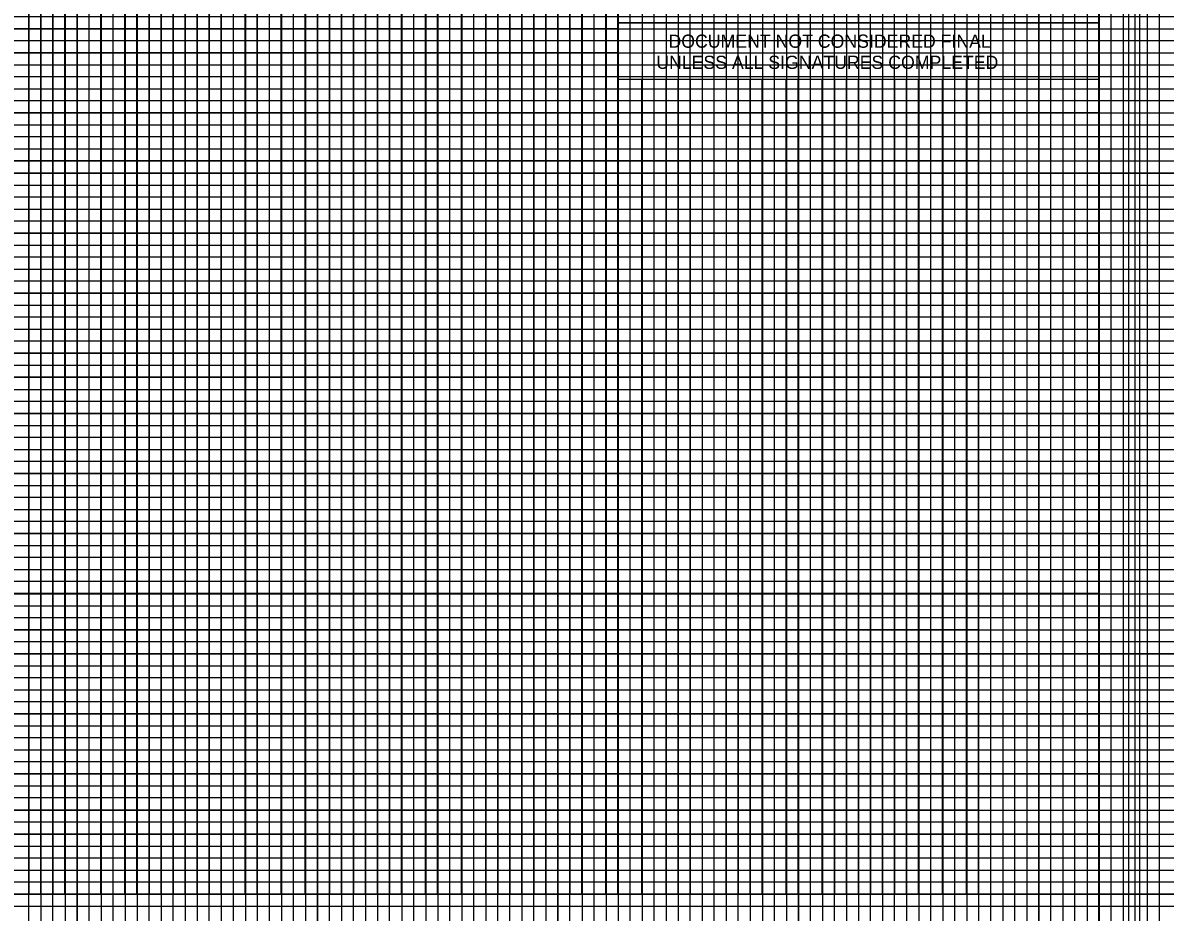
# Model space of a CAD drawing. Extents: x 553912 to 567693, y 512355 to 537539.
# Drawn here: x 566753.9 to 567228.9, y 513957.2 to 514327.2 of the extents above; entities that cross this region are included whole.
import ezdxf

# ---------------------------------------------------------------- set-up
doc = ezdxf.new("R2010")
doc.units = 0
for name, color, linetype in [('Old_Level_42', 7, 'Continuous'), ('Old_Level_54', 7, 'Continuous'), ('Prop ROW Permanent Easement CELL', 7, 'Continuous'), ('Sheet DOT Grid CELL', 7, 'Continuous'), ('Sheet Layout Profile Border Port 1', 7, 'Continuous'), ('Sheet Plot Border Inside CELL', 7, 'Continuous'), ('Sheet Plot Border Outside CELL', 7, 'Continuous'), ('Sheet Profile CELL', 7, 'Continuous'), ('Sheet Profile Grid Major CELL', 7, 'Continuous'), ('Sheet Profile Grid Middle CELL', 7, 'Continuous'), ('Sheet Profile Grid Minor CELL', 7, 'Continuous'), ('Sheet Sticker Exception Certification CELL', 7, 'Continuous'), ('Sheet Summary Guardrail CELL', 7, 'Continuous')]:
    doc.layers.add(name, color=color, linetype=linetype)

msp = doc.modelspace()

# ---------------------------------------------------------------- linework, layer by layer
at = {"layer": 'Old_Level_42'}
for p, q in [((566776.42, 514839.71), (566776.42, 513814.71)), ((566826.42, 514839.71), (566826.42, 513814.71)), ((566876.42, 514839.71), (566876.42, 513814.71)), ((566926.42, 514839.71), (566926.42, 513814.71)), ((566976.42, 514839.71), (566976.42, 513814.71)), ((567026.42, 514839.71), (567026.42, 513814.71)), ((567076.42, 514839.71), (567076.42, 513814.71)), ((567126.42, 514839.71), (567126.42, 513814.71)), ((567176.42, 514839.71), (567176.42, 513814.71)), ((567226.42, 514839.71), (567226.42, 513814.71)), ((566176.42, 514314.71), (567676.42, 514314.71)), ((566176.42, 514264.71), (567676.42, 514264.71)), ((566176.42, 514214.71), (567676.42, 514214.71)), ((566176.42, 514164.71), (567676.42, 514164.71)), ((566176.42, 514114.71), (567676.42, 514114.71)), ((566176.42, 514064.71), (567676.42, 514064.71)), ((566176.42, 514014.71), (567676.42, 514014.71)), ((566176.42, 513964.71), (567676.42, 513964.71))]:
    msp.add_line(p, q, dxfattribs=at)
at = {"layer": 'Old_Level_54'}
for points in [[(566776.42, 513814.71), (566776.42, 514839.71), (566826.42, 514839.71), (566826.42, 513814.71)], [(566876.42, 513814.71), (566876.42, 514839.71), (566926.42, 514839.71), (566926.42, 513814.71)], [(566976.42, 513814.71), (566976.42, 514839.71), (567026.42, 514839.71), (567026.42, 513814.71)], [(567076.42, 513814.71), (567076.42, 514839.71), (567126.42, 514839.71), (567126.42, 513814.71)], [(567176.42, 513814.71), (567176.42, 514839.71), (567226.42, 514839.71), (567226.42, 513814.71)], [(567676.42, 514264.71), (566176.42, 514264.71), (566176.42, 514314.71), (567676.42, 514314.71)], [(567676.42, 514164.71), (566176.42, 514164.71), (566176.42, 514214.71), (567676.42, 514214.71)], [(567676.42, 514064.71), (566176.42, 514064.71), (566176.42, 514114.71), (567676.42, 514114.71)], [(567676.42, 513964.71), (566176.42, 513964.71), (566176.42, 514014.71), (567676.42, 514014.71)]]:
    msp.add_lwpolyline(points, dxfattribs=at)
at = {"layer": 'Prop ROW Permanent Easement CELL'}
for points in [[(566751.42, 514839.71), (566801.42, 514839.71), (566801.42, 513814.71)], [(566851.42, 513814.71), (566851.42, 514839.71), (566901.42, 514839.71), (566901.42, 513814.71)], [(566951.42, 513814.71), (566951.42, 514839.71), (567001.42, 514839.71), (567001.42, 513814.71)], [(567051.42, 513814.71), (567051.42, 514839.71), (567101.42, 514839.71), (567101.42, 513814.71)], [(567151.42, 513814.71), (567151.42, 514839.71), (567201.42, 514839.71), (567201.42, 513814.71)], [(567676.42, 514339.71), (566176.42, 514339.71), (566176.42, 514289.71), (567676.42, 514289.71)], [(567676.42, 514239.71), (566176.42, 514239.71), (566176.42, 514189.71), (567676.42, 514189.71)], [(567676.42, 514139.71), (566176.42, 514139.71), (566176.42, 514089.71), (567676.42, 514089.71)], [(567676.42, 514039.71), (566176.42, 514039.71), (566176.42, 513989.71), (567676.42, 513989.71)]]:
    msp.add_lwpolyline(points, dxfattribs=at)
at = {"layer": 'Sheet DOT Grid CELL'}
for p, q in [((566801.35, 513964.72), (566801.35, 514464.72)), ((566851.35, 513964.72), (566851.35, 514464.72)), ((566901.35, 513964.72), (566901.35, 514464.72)), ((566951.35, 513964.72), (566951.35, 514464.72)), ((567001.35, 513964.72), (567001.35, 514327.17)), ((567001.35, 514314.72), (565701.35, 514314.72)), ((567051.35, 513964.72), (567051.35, 514303.67)), ((567101.35, 513964.72), (567101.35, 514303.67)), ((567151.35, 513964.72), (567151.35, 514303.67)), ((567201.35, 514264.72), (565701.35, 514264.72)), ((567201.35, 514214.72), (565701.35, 514214.72)), ((567201.35, 514164.72), (565701.35, 514164.72)), ((567201.35, 514114.72), (565701.35, 514114.72)), ((567201.35, 514064.72), (565701.35, 514064.72)), ((567201.35, 514014.72), (565701.35, 514014.72))]:
    msp.add_line(p, q, dxfattribs=at)
at = {"layer": 'Sheet Layout Profile Border Port 1'}
msp.add_lwpolyline([(565751.35, 514303.67), (565751.35, 513964.72), (567151.35, 513964.72), (567151.35, 514303.67)], dxfattribs=at)
at = {"layer": 'Sheet Plot Border Inside CELL'}
msp.add_lwpolyline([(565547.35, 513412.17), (567213.85, 513412.17), (567213.85, 514467.27), (565547.35, 514467.27)], close=True, dxfattribs=at)
at = {"layer": 'Sheet Plot Border Outside CELL'}
msp.add_lwpolyline([(565534.35, 513389.72), (567218.35, 513389.72), (567218.35, 514489.72), (565534.35, 514489.72)], close=True, dxfattribs=at)
at = {"layer": 'Sheet Profile CELL'}
msp.add_line((565701.35, 513964.72), (567201.35, 513964.72), dxfattribs=at)
for points in [[(567201.35, 514464.72), (565701.35, 514464.72), (565701.35, 513414.72), (567201.35, 513414.72)], [(567001.3, 514439.67), (567101.35, 514439.67), (567101.35, 514327.17), (567001.3, 514327.17)], [(567101.35, 514439.67), (567201.35, 514439.67), (567201.35, 514327.17), (567101.35, 514327.17)]]:
    msp.add_lwpolyline(points, close=True, dxfattribs=at)
at = {"layer": 'Sheet Profile Grid Major CELL'}
for points in [[(566751.35, 513964.72), (566801.35, 513964.72), (566801.35, 514464.72), (566851.35, 514464.72), (566851.35, 513964.72), (566901.35, 513964.72), (566901.35, 514464.72), (566951.35, 514464.72), (566951.35, 513964.72), (567001.35, 513964.72), (567001.35, 514464.72), (567027.65, 514464.72)], [(567001.35, 514364.72), (565701.35, 514364.72), (565701.35, 514314.72), (567001.35, 514314.72)], [(567151.35, 514303.67), (567151.35, 513964.72), (567201.35, 513964.72), (567201.35, 514314.72)], [(567051.35, 514303.67), (567051.35, 513964.72), (567101.35, 513964.72), (567101.35, 513964.72), (567101.35, 514303.67)], [(567201.35, 514264.72), (565701.35, 514264.72), (565701.35, 514214.72), (567201.35, 514214.72)], [(567201.35, 514164.72), (565701.35, 514164.72), (565701.35, 514114.72), (567201.35, 514114.72)], [(567201.35, 514064.72), (565701.35, 514064.72), (565701.35, 514064.72), (565701.35, 514014.72), (567201.35, 514014.72)]]:
    msp.add_lwpolyline(points, dxfattribs=at)
at = {"layer": 'Sheet Profile Grid Middle CELL'}
for points in [[(566726.35, 514464.72), (566776.35, 514464.72), (566776.35, 513964.72), (566826.35, 513964.72), (566826.35, 514464.72), (566876.35, 514464.72), (566876.35, 513964.72), (566926.35, 513964.72), (566926.35, 514464.72), (566976.35, 514464.72), (566976.35, 513964.72), (567026.35, 513964.72), (567026.35, 514303.67)], [(567026.35, 514227.52), (567026.35, 513964.72), (567076.35, 513964.72), (567076.35, 514303.67)], [(567076.35, 514227.52), (567076.35, 513964.72), (567126.35, 513964.72), (567126.35, 514303.67)], [(567201.35, 514289.72), (565701.35, 514289.72), (565701.35, 514239.72), (567026.35, 514239.72)], [(567026.35, 514239.72), (567201.35, 514239.72)], [(567201.35, 514189.72), (565701.35, 514189.72), (565701.35, 514139.72), (567201.35, 514139.72)], [(567201.35, 514089.72), (565701.35, 514089.72), (565701.35, 514039.72), (567201.35, 514039.72)], [(567201.35, 513989.72), (565701.35, 513989.72)]]:
    msp.add_lwpolyline(points, dxfattribs=at)
at = {"layer": 'Sheet Profile Grid Minor CELL'}
for p, q in [((567001.35, 514324.72), (565751.35, 514324.72)), ((567001.35, 514319.72), (565751.35, 514319.72)), ((565751.35, 514309.72), (567001.35, 514309.72)), ((567001.35, 514304.72), (565751.35, 514304.72)), ((565751.35, 514299.72), (567151.35, 514299.72)), ((567151.35, 514279.72), (565751.35, 514279.72)), ((565751.35, 514274.72), (567151.35, 514274.72)), ((567151.35, 514254.72), (565751.35, 514254.72)), ((565751.35, 514249.72), (567151.35, 514249.72)), ((567151.35, 514229.72), (565751.35, 514229.72)), ((565751.35, 514224.72), (567151.35, 514224.72)), ((567151.35, 514219.72), (565751.35, 514219.72)), ((565751.35, 514209.72), (567151.35, 514209.72)), ((567151.35, 514204.72), (565751.35, 514204.72)), ((565751.35, 514199.72), (567151.35, 514199.72)), ((567151.35, 514194.72), (565751.35, 514194.72)), ((565751.35, 514184.72), (567151.35, 514184.72)), ((567151.35, 514179.72), (565751.35, 514179.72)), ((565751.35, 514174.72), (567151.35, 514174.72)), ((567151.35, 514169.72), (565751.35, 514169.72)), ((565751.35, 514159.72), (567151.35, 514159.72)), ((567151.35, 514154.72), (565751.35, 514154.72)), ((565751.35, 514149.72), (567151.35, 514149.72)), ((567151.35, 514144.72), (565751.35, 514144.72)), ((565751.35, 514134.72), (567151.35, 514134.72)), ((567151.35, 514129.72), (565751.35, 514129.72)), ((565751.35, 514124.72), (567151.35, 514124.72)), ((567151.35, 514119.72), (565751.35, 514119.72)), ((565751.35, 514109.72), (567151.35, 514109.72)), ((567151.35, 514104.72), (565751.35, 514104.72)), ((565751.35, 514099.72), (567151.35, 514099.72)), ((567151.35, 514094.72), (565751.35, 514094.72)), ((565751.35, 514084.72), (567151.35, 514084.72)), ((567151.35, 514079.72), (565751.35, 514079.72)), ((567151.35, 514074.72), (565751.35, 514074.72)), ((567151.35, 514069.72), (565751.35, 514069.72)), ((565751.35, 514059.72), (567151.35, 514059.72)), ((567151.35, 514054.72), (565751.35, 514054.72)), ((565751.35, 514049.72), (567151.35, 514049.72)), ((567151.35, 514044.72), (565751.35, 514044.72)), ((565751.35, 514034.72), (567151.35, 514034.72)), ((567151.35, 514029.72), (565751.35, 514029.72)), ((565751.35, 514024.72), (567151.35, 514024.72)), ((567151.35, 514019.72), (565751.35, 514019.72)), ((565751.35, 514009.72), (567151.35, 514009.72)), ((567151.35, 514004.72), (565751.35, 514004.72)), ((565751.35, 513999.72), (567151.35, 513999.72)), ((567151.35, 513994.72), (565751.35, 513994.72)), ((565751.35, 513984.72), (567151.35, 513984.72)), ((567151.35, 513979.72), (565751.35, 513979.72)), ((565751.35, 513974.72), (567151.35, 513974.72))]:
    msp.add_line(p, q, dxfattribs=at)
for points in [[(566756.35, 514464.72), (566756.35, 513964.72), (566761.35, 513964.72), (566761.35, 514464.72)], [(566766.35, 514464.72), (566766.35, 513964.72), (566771.35, 513964.72), (566771.35, 514464.72)], [(566781.35, 514464.72), (566781.35, 513964.72), (566786.35, 513964.72), (566786.35, 514464.72)], [(566791.35, 514464.72), (566791.35, 513964.72), (566796.35, 513964.72), (566796.35, 514464.72)], [(566806.35, 514464.72), (566806.35, 513964.72), (566811.35, 513964.72), (566811.35, 514464.72)], [(566816.35, 514464.72), (566816.35, 513964.72), (566821.35, 513964.72), (566821.35, 514464.72)], [(566831.35, 514464.72), (566831.35, 513964.72), (566836.35, 513964.72), (566836.35, 514464.72)], [(566841.35, 514464.72), (566841.35, 513964.72), (566846.35, 513964.72), (566846.35, 514464.72)], [(566856.35, 514464.72), (566856.35, 513964.72), (566861.35, 513964.72), (566861.35, 514464.72)], [(566866.35, 514464.72), (566866.35, 513964.72), (566871.35, 513964.72), (566871.35, 514464.72)], [(566881.35, 514464.72), (566881.35, 513964.72), (566886.35, 513964.72), (566886.35, 514464.72)], [(566891.35, 514464.72), (566891.35, 513964.72)], [(566891.35, 513964.72), (566896.35, 513964.72), (566896.35, 514464.72)], [(566906.35, 514464.72), (566906.35, 513964.72), (566911.35, 513964.72), (566911.35, 514464.72)], [(566916.35, 514464.72), (566916.35, 513964.72), (566921.35, 513964.72), (566921.35, 514464.72)], [(566931.35, 514464.72), (566931.35, 513964.72), (566936.35, 513964.72), (566936.35, 514464.72)], [(566941.35, 514464.72), (566941.35, 513964.72), (566946.35, 513964.72), (566946.35, 514464.72)], [(566956.35, 514464.72), (566956.35, 513964.72), (566961.35, 513964.72), (566961.35, 514464.72)], [(566966.35, 514464.72), (566966.35, 513964.72), (566971.35, 513964.72), (566971.35, 514464.72)], [(566981.35, 514464.72), (566981.35, 513964.72), (566986.35, 513964.72), (566986.35, 514464.72)], [(566991.35, 514464.72), (566991.35, 513964.72), (566996.35, 513964.72), (566996.35, 514464.72)], [(567006.35, 514303.67), (567006.35, 513964.72), (567011.35, 513964.72), (567011.35, 514303.67)], [(567016.35, 514303.67), (567016.35, 513964.72), (567021.35, 513964.72), (567021.35, 514303.67)], [(567031.35, 514303.67), (567031.35, 513964.72), (567031.35, 513964.72), (567036.35, 513964.72), (567041.35, 513964.72), (567041.35, 514303.67)], [(567036.35, 514303.67), (567036.35, 513964.72)], [(567046.35, 514303.67), (567046.25, 513964.77), (567051.25, 513964.77), (567056.35, 513964.72), (567056.35, 514303.67)], [(567056.35, 514227.52), (567056.35, 513964.72), (567061.35, 513964.72), (567061.35, 514303.67)], [(567066.35, 514303.67), (567066.35, 513964.72), (567071.35, 513964.72), (567071.35, 514303.67)], [(567081.35, 514303.67), (567081.35, 513964.72), (567086.35, 513964.72), (567086.35, 514303.67)], [(567091.35, 514303.67), (567091.35, 513964.72), (567096.35, 513964.72), (567096.35, 514303.67)], [(567106.35, 514303.67), (567106.35, 513964.72), (567111.35, 513964.72), (567111.35, 514303.67)], [(567116.35, 514303.67), (567116.35, 513964.72), (567121.35, 513964.72), (567121.35, 514303.67)], [(567131.35, 514303.67), (567131.35, 513964.72), (567136.35, 513964.72), (567136.35, 514303.67)], [(567141.35, 514303.67), (567141.35, 513964.72), (567146.35, 513964.72), (567146.35, 514303.67)], [(567151.35, 514294.72), (565751.35, 514294.72), (565751.35, 514284.72), (567151.35, 514284.72)], [(567151.35, 514269.72), (565751.35, 514269.72), (565751.35, 514259.72), (567151.35, 514259.72)], [(567151.35, 514244.72), (565751.35, 514244.72), (565751.35, 514234.72), (567151.35, 514234.72)], [(567151.35, 513969.72), (565751.35, 513969.72)]]:
    msp.add_lwpolyline(points, dxfattribs=at)
at = {"layer": 'Sheet Sticker Exception Certification CELL'}
for p, q in [((567001.3, 514303.67), (567001.3, 514327.17)), ((567001.3, 514327.17), (567201.34, 514327.17)), ((567001.3, 514303.67), (567001.3, 514327.17)), ((567001.3, 514327.17), (567201.34, 514327.17)), ((567201.34, 514327.16), (567201.34, 514303.66)), ((567201.34, 514327.16), (567201.34, 514303.66)), ((567201.34, 514303.67), (567001.3, 514303.67)), ((567201.34, 514303.67), (567001.3, 514303.67))]:
    msp.add_line(p, q, dxfattribs=at)
at = {"layer": 'Sheet Summary Guardrail CELL'}
for points in [[(566756.42, 513814.71), (566756.42, 514839.71), (566761.42, 514839.71), (566761.42, 513814.71)], [(566766.42, 513814.71), (566766.42, 514839.71), (566771.42, 514839.71), (566771.42, 513814.71)], [(566781.42, 513814.71), (566781.42, 514839.71), (566786.42, 514839.71), (566786.42, 513814.71)], [(566791.42, 513814.71), (566791.42, 514839.71), (566796.42, 514839.71), (566796.42, 513814.71)], [(566806.42, 513814.71), (566806.42, 514839.71), (566811.42, 514839.71), (566811.42, 513814.71)], [(566816.42, 513814.71), (566816.42, 514839.71), (566821.42, 514839.71), (566821.42, 513814.71)], [(566831.42, 513814.71), (566831.42, 514839.71), (566836.42, 514839.71), (566836.42, 513814.71)], [(566841.42, 513814.71), (566841.42, 514839.71), (566846.42, 514839.71), (566846.42, 513814.71)], [(566856.42, 513814.71), (566856.42, 514839.71), (566861.42, 514839.71), (566861.42, 513814.71)], [(566866.42, 513814.71), (566866.42, 514839.71), (566871.42, 514839.71), (566871.42, 513814.71)], [(566881.42, 513814.71), (566881.42, 514839.71), (566886.42, 514839.71), (566886.42, 513814.71)], [(566891.42, 513814.71), (566891.42, 514839.71), (566896.42, 514839.71), (566896.42, 513814.71)], [(566906.42, 513814.71), (566906.42, 514839.71), (566911.42, 514839.71), (566911.42, 513814.71)], [(566916.42, 513814.71), (566916.42, 514839.71), (566921.42, 514839.71), (566921.42, 513814.71)], [(566931.42, 513814.71), (566931.42, 514839.71), (566936.42, 514839.71), (566936.42, 513814.71)], [(566941.42, 513814.71), (566941.42, 514839.11), (566946.42, 514839.11), (566946.42, 513814.71)], [(566956.42, 513814.71), (566956.42, 514839.71), (566961.42, 514839.71), (566961.42, 513814.71)], [(566966.42, 513814.71), (566966.42, 514839.71), (566971.42, 514839.71), (566971.42, 513814.71)], [(566981.42, 513814.71), (566981.42, 514839.71), (566986.42, 514839.71), (566986.42, 513814.71)], [(566991.42, 513814.71), (566991.42, 514839.71), (566996.42, 514839.71), (566996.42, 513814.71)], [(567006.42, 513814.71), (567006.42, 514839.71), (567011.42, 514839.71), (567011.42, 513814.71)], [(567016.42, 513814.71), (567016.42, 514839.71), (567021.42, 514839.71), (567021.42, 513814.71)], [(567031.42, 513814.71), (567031.42, 514839.71), (567036.42, 514839.71), (567036.42, 513814.71)], [(567041.42, 513814.71), (567041.42, 514839.71), (567046.42, 514839.71), (567046.42, 513814.71)], [(567056.42, 513814.71), (567056.42, 514839.71), (567061.42, 514839.71), (567061.42, 513814.71)], [(567066.42, 513814.71), (567066.42, 514839.71), (567071.42, 514839.71), (567071.42, 513814.71)], [(567081.42, 513814.71), (567081.42, 514839.71), (567086.42, 514839.71), (567086.42, 513814.71)], [(567091.42, 513814.71), (567091.42, 514839.71), (567096.42, 514839.71), (567096.42, 513814.71)], [(567106.42, 513814.71), (567106.42, 514839.71), (567111.42, 514839.71), (567111.42, 513814.71)], [(567116.42, 513814.71), (567116.42, 514839.71), (567121.42, 514839.71), (567121.42, 513814.71)], [(567131.42, 513814.71), (567131.42, 514839.71), (567136.42, 514839.71), (567136.42, 513814.71)], [(567141.42, 513814.71), (567141.42, 514839.71), (567146.42, 514839.71), (567146.42, 513814.71)], [(567156.42, 513814.71), (567156.42, 514839.71), (567161.42, 514839.71), (567161.42, 513814.71)], [(567166.42, 513814.71), (567166.42, 514839.71), (567171.42, 514839.71), (567171.42, 513814.71)], [(567181.42, 513814.71), (567181.42, 514839.71), (567186.42, 514839.71), (567186.42, 513814.71)], [(567191.42, 513814.71), (567191.42, 514839.71), (567196.42, 514839.71), (567196.42, 513814.71)], [(567206.42, 513814.71), (567206.42, 514839.71), (567211.42, 514839.71), (567211.42, 513814.71)], [(567216.42, 513814.71), (567216.42, 514839.71), (567221.42, 514839.71), (567221.42, 513814.71)], [(567626.42, 514329.71), (566226.42, 514329.71), (566226.42, 514324.71), (567626.42, 514324.71)], [(567626.42, 514319.71), (566226.42, 514319.71)], [(566226.42, 514309.71), (567626.42, 514309.71)], [(567626.42, 514304.71), (566226.42, 514304.71), (566226.42, 514299.71), (567626.42, 514299.71)], [(567626.42, 514294.71), (566226.42, 514294.71), (566226.42, 514284.71), (567626.42, 514284.71)], [(567626.42, 514279.71), (566226.42, 514279.71), (566226.42, 514274.71), (567626.42, 514274.71)], [(567626.42, 514269.71), (566226.42, 514269.71), (566226.42, 514259.71), (567626.42, 514259.71)], [(567626.42, 514254.71), (566226.42, 514254.71), (566226.42, 514249.71), (567626.42, 514249.71)], [(567626.42, 514244.71), (566226.42, 514244.71), (566226.42, 514234.71), (567626.42, 514234.71)], [(567626.42, 514229.71), (566226.42, 514229.71), (566226.42, 514224.71), (567626.42, 514224.71)], [(567626.42, 514219.71), (566226.42, 514219.71), (566226.42, 514209.71), (567626.42, 514209.71)], [(567626.42, 514204.71), (566226.42, 514204.71), (566226.42, 514199.71), (567626.42, 514199.71)], [(567626.42, 514194.71), (566226.42, 514194.71), (566226.42, 514184.71), (567626.42, 514184.71)], [(567626.42, 514179.71), (566226.42, 514179.71), (566226.42, 514174.71), (567626.42, 514174.71)], [(567626.42, 514169.71), (566226.42, 514169.71), (566226.42, 514159.71), (567626.42, 514159.71)], [(567626.42, 514154.71), (566226.42, 514154.71), (566226.42, 514149.71), (567626.42, 514149.71)], [(567626.42, 514144.71), (566226.42, 514144.71), (566226.42, 514134.71), (567626.42, 514134.71)], [(567626.42, 514129.71), (566226.42, 514129.71), (566226.42, 514124.71), (567626.42, 514124.71)], [(567626.42, 514119.71), (566226.42, 514119.71), (566226.42, 514109.71), (567626.42, 514109.71)], [(567626.42, 514104.71), (566226.42, 514104.71), (566226.42, 514099.71), (567626.42, 514099.71)], [(567626.42, 514094.71), (566226.42, 514094.71), (566226.42, 514084.71), (567626.42, 514084.71)], [(567626.42, 514079.71), (566226.42, 514079.71), (566226.42, 514074.71), (567626.42, 514074.71)], [(567626.42, 514069.71), (566226.42, 514069.71), (566226.42, 514059.71), (567626.42, 514059.71)], [(567626.42, 514054.71), (566226.42, 514054.71), (566226.42, 514049.71), (567626.42, 514049.71)], [(567626.42, 514044.71), (566226.42, 514044.71), (566226.42, 514034.71), (567626.42, 514034.71)], [(567626.42, 514029.71), (566226.42, 514029.71), (566226.42, 514024.71), (567626.42, 514024.71)], [(567626.42, 514019.71), (566226.42, 514019.71)], [(566226.42, 514009.71), (567626.42, 514009.71)], [(567626.42, 514004.71), (566226.42, 514004.71), (566226.42, 513999.71), (567626.42, 513999.71)], [(567626.42, 513994.71), (566226.42, 513994.71)], [(566226.42, 513984.71), (567626.42, 513984.71)], [(567626.42, 513979.71), (566226.42, 513979.71), (566226.42, 513974.71), (567626.42, 513974.71)], [(567626.42, 513969.71), (566226.42, 513969.71), (566226.42, 513959.71), (567626.42, 513959.71)]]:
    msp.add_lwpolyline(points, dxfattribs=at)

# ---------------------------------------------------------------- texts
at = {"layer": 'Sheet Sticker Exception Certification CELL'}
for s, p in [('DOCUMENT NOT CONSIDERED FINAL', (567022.38, 514316.82)), ('DOCUMENT NOT CONSIDERED FINAL', (567022.38, 514316.82)), ('UNLESS ALL SIGNATURES COMPLETED', (567017.3, 514308.02)), ('UNLESS ALL SIGNATURES COMPLETED', (567017.3, 514308.02))]:
    msp.add_text(s, height=5.5, dxfattribs=at).set_placement(p)

doc.saveas('drawing.dxf')
